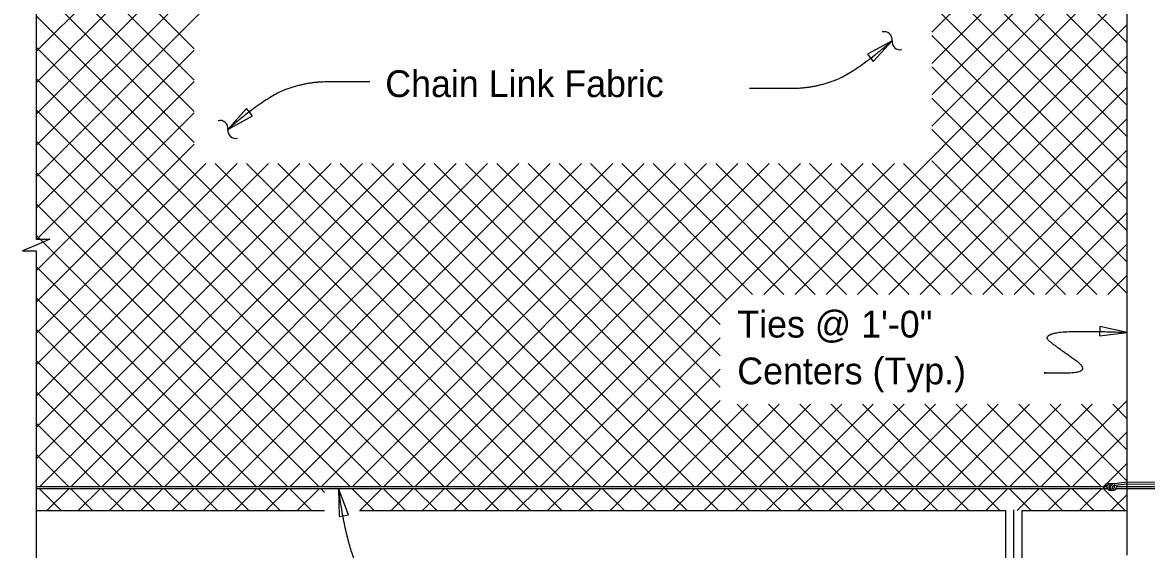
# Model space of a CAD drawing. Extents: x 0 to 41.1, y 0 to 25.9.
# Drawn here: x 16.15 to 24.62, y 16.93 to 20.9 of the extents above; entities that cross this region are included whole.
import ezdxf

# ---------------------------------------------------------------- set-up
doc = ezdxf.new("R2010")
doc.units = 0
for name, color, linetype in [('CL_Major', 7, 'Continuous'), ('Dimension', 7, 'Continuous'), ('Miscellaneous', 7, 'Continuous'), ('SteelMisc', 7, 'Continuous'), ('SteelMisc_h', 7, 'Continuous'), ('SupstrConc', 7, 'Continuous'), ('TextStructures', 7, 'Continuous')]:
    doc.layers.add(name, color=color, linetype=linetype)

msp = doc.modelspace()

# ---------------------------------------------------------------- linework, layer by layer
at = {"layer": 'CL_Major'}
msp.add_line((23.6151, 11.6734), (23.6151, 17.2313), dxfattribs=at)
at = {"layer": 'Dimension'}
for points in [[(16.252, 23.2265), (16.252, 21.2702), (16.3553, 21.2702), (16.252, 21.2252), (16.1487, 21.1802), (16.252, 21.1802), (16.252, 20.2867)], [(16.252, 20.2867), (16.252, 19.2689), (16.3553, 19.2689), (16.252, 19.2239), (16.1487, 19.1789), (16.252, 19.1789), (16.252, 16.9746)], [(16.252, 17.2246), (16.252, 15.3737), (16.3553, 15.3737), (16.252, 15.3287), (16.1487, 15.2837), (16.252, 15.2837), (16.252, 13.2829)]]:
    msp.add_lwpolyline(points, dxfattribs=at)
for points in [[(22.699, 20.7612), (22.5135, 20.6603), (22.5571, 20.6048)], [(17.695, 20.0946), (17.8805, 20.1956), (17.8369, 20.251)], [(24.4692, 18.5661), (24.2626, 18.6099), (24.2597, 18.5394)], [(18.5297, 17.3912), (18.5346, 17.18), (18.6039, 17.1934)]]:
    msp.add_lwpolyline(points, close=True, dxfattribs=at)
for centre, start, end in [((22.6394, 20.7697), 352.34263, 104.06985), ((22.7576, 20.7538), 172.34263, 284.06985), ((17.6364, 20.102), 352.34263, 104.06985), ((17.7546, 20.0861), 172.34263, 284.06985)]:
    msp.add_arc(centre, 0.0596, start, end, dxfattribs=at)
for points in [[(21.6258, 20.4048), (21.8279, 20.4048), (22.1015, 20.4048), (22.4083, 20.5127), (22.6984, 20.7617)], [(18.7638, 20.451), (18.5661, 20.451), (18.2925, 20.451), (17.9858, 20.3431), (17.6956, 20.0941)], [(23.8587, 18.2615), (23.7933, 18.2615), (24.2134, 18.2615), (23.9631, 18.4386), (23.826, 18.5413), (24.0365, 18.5838), (24.4692, 18.5661)], [(19.1927, 16.5972), (18.7949, 16.5972), (18.5909, 16.9342), (18.5297, 17.3911)]]:
    msp.add_open_spline(points, degree=2, dxfattribs=at)
at = {"layer": 'Miscellaneous'}
for p, q in [((16.252, 19.7364), (19.5586, 23.0431)), ((16.252, 20.2078), (19.0872, 23.0431)), ((16.252, 20.6792), (18.6158, 23.0431)), ((16.252, 19.9721), (19.3229, 23.0431)), ((16.252, 20.4435), (18.8515, 23.0431)), ((20.9925, 23.0431), (24.4692, 19.5664)), ((21.2282, 23.0431), (24.4692, 19.8021)), ((21.4639, 23.0431), (24.4692, 20.0378)), ((21.6996, 23.0431), (24.4692, 20.2735)), ((21.9353, 23.0431), (24.4692, 20.5092)), ((22.1711, 23.0431), (24.4692, 20.7449)), ((22.9985, 20.8261), (24.4692, 22.2968)), ((22.9985, 20.5904), (24.4692, 22.0611)), ((16.252, 21.8911), (17.4417, 20.7014)), ((22.9985, 20.3547), (24.4692, 21.8254)), ((16.252, 21.6554), (17.4417, 20.4657)), ((22.9985, 20.119), (24.4692, 21.5897)), ((16.252, 21.4197), (17.4417, 20.23)), ((21.9677, 18.8525), (24.4692, 21.354)), ((16.2232, 21.2127), (17.4417, 19.9943)), ((22.2034, 18.8525), (24.4692, 21.1183)), ((16.252, 20.9483), (19.7943, 17.4059)), ((22.4391, 18.8525), (24.4692, 20.8826)), ((22.9985, 20.8014), (24.4692, 19.3307)), ((16.252, 20.7126), (19.5586, 17.4059)), ((16.252, 19.5007), (17.4417, 20.6904)), ((22.6748, 18.8525), (24.4692, 20.6469)), ((22.9985, 20.5657), (24.4692, 19.095)), ((16.252, 20.4769), (19.3229, 17.4059)), ((16.2558, 19.2689), (17.4417, 20.4547)), ((22.9105, 18.8525), (24.4692, 20.4112)), ((22.9985, 20.33), (24.4692, 18.8593)), ((16.252, 20.2412), (19.0872, 17.4059)), ((16.252, 19.0293), (17.4417, 20.219)), ((23.1462, 18.8525), (24.4692, 20.1755)), ((22.9985, 20.0943), (24.2403, 18.8525)), ((16.252, 20.0055), (18.8515, 17.4059)), ((16.252, 18.7936), (17.4417, 19.9833)), ((23.3819, 18.8525), (24.4692, 19.9398)), ((16.252, 17.8508), (18.2378, 19.8366)), ((16.252, 18.3222), (17.7664, 19.8366)), ((16.252, 18.5579), (17.5307, 19.8366)), ((16.252, 18.0865), (18.0021, 19.8366)), ((16.252, 17.6151), (18.4735, 19.8366)), ((16.2785, 17.4059), (18.7092, 19.8366)), ((16.5142, 17.4059), (18.9449, 19.8366)), ((16.7499, 17.4059), (19.1806, 19.8366)), ((16.9856, 17.4059), (19.4163, 19.8366)), ((17.2213, 17.4059), (19.652, 19.8366)), ((17.457, 17.4059), (19.8877, 19.8366)), ((17.5994, 19.8366), (20.03, 17.4059)), ((17.6927, 17.4059), (20.1234, 19.8366)), ((17.8351, 19.8366), (20.2657, 17.4059)), ((17.9284, 17.4059), (20.3591, 19.8366)), ((18.0708, 19.8366), (20.5014, 17.4059)), ((18.1641, 17.4059), (20.5948, 19.8366)), ((18.3065, 19.8366), (20.7372, 17.4059)), ((18.3998, 17.4059), (20.8305, 19.8366)), ((18.5422, 19.8366), (21.0907, 17.2881)), ((18.6355, 17.4059), (21.0662, 19.8366)), ((18.7779, 19.8366), (21.2086, 17.4059)), ((18.8712, 17.4059), (21.3019, 19.8366)), ((19.0136, 19.8366), (21.4443, 17.4059)), ((19.1069, 17.4059), (21.5376, 19.8366)), ((19.2493, 19.8366), (21.68, 17.4059)), ((19.3426, 17.4059), (21.7733, 19.8366)), ((19.485, 19.8366), (21.9157, 17.4059)), ((19.5783, 17.4059), (22.009, 19.8366)), ((19.6962, 17.2881), (22.2447, 19.8366)), ((19.7207, 19.8366), (21.4039, 18.1533)), ((19.9564, 19.8366), (21.4039, 18.389)), ((20.0497, 17.4059), (22.4804, 19.8366)), ((20.1921, 19.8366), (21.4039, 18.6247)), ((20.4278, 19.8366), (21.4541, 18.8103)), ((20.6635, 19.8366), (21.6476, 18.8525)), ((20.8992, 19.8366), (21.8833, 18.8525)), ((21.1349, 19.8366), (22.119, 18.8525)), ((21.3706, 19.8366), (22.3547, 18.8525)), ((21.6063, 19.8366), (22.5904, 18.8525)), ((21.732, 18.8525), (22.7161, 19.8366)), ((21.842, 19.8366), (22.8261, 18.8525)), ((22.0777, 19.8366), (23.0618, 18.8525)), ((22.3134, 19.8366), (23.2975, 18.8525)), ((22.5491, 19.8366), (23.5332, 18.8525)), ((22.7848, 19.8366), (23.7689, 18.8525)), ((22.9985, 19.8586), (24.0046, 18.8525)), ((16.252, 19.7698), (18.6158, 17.4059)), ((23.6176, 18.8525), (24.4692, 19.7041)), ((16.252, 19.5341), (18.3801, 17.4059)), ((23.8533, 18.8525), (24.4692, 19.4684)), ((16.252, 19.2984), (18.1444, 17.4059)), ((24.089, 18.8525), (24.4692, 19.2327)), ((16.252, 19.0627), (17.9087, 17.4059)), ((24.3247, 18.8525), (24.4692, 18.997)), ((16.252, 18.827), (17.673, 17.4059)), ((16.252, 18.5913), (17.4373, 17.4059)), ((20.2854, 17.4059), (21.4039, 18.5244)), ((16.252, 18.3556), (17.2016, 17.4059)), ((20.5211, 17.4059), (21.4039, 18.2887)), ((16.252, 18.1198), (16.9659, 17.4059)), ((20.7568, 17.4059), (21.4039, 18.053)), ((23.821, 17.4059), (24.4692, 18.0542)), ((20.9925, 17.4059), (21.6122, 18.0255)), ((21.2282, 17.4059), (21.8479, 18.0255)), ((21.4639, 17.4059), (22.0836, 18.0255)), ((21.5318, 18.0255), (22.1514, 17.4059)), ((21.6996, 17.4059), (22.3193, 18.0255)), ((21.7675, 18.0255), (22.3871, 17.4059)), ((21.9353, 17.4059), (22.555, 18.0255)), ((22.0032, 18.0255), (22.6228, 17.4059)), ((22.1711, 17.4059), (22.7907, 18.0255)), ((22.2389, 18.0255), (22.8585, 17.4059)), ((22.4068, 17.4059), (23.0264, 18.0255)), ((22.4746, 18.0255), (23.0942, 17.4059)), ((22.6425, 17.4059), (23.2621, 18.0255)), ((22.7103, 18.0255), (23.3299, 17.4059)), ((22.8782, 17.4059), (23.4978, 18.0255)), ((22.946, 18.0255), (23.5656, 17.4059)), ((23.1139, 17.4059), (23.7335, 18.0255)), ((23.1817, 18.0255), (23.8013, 17.4059)), ((23.3496, 17.4059), (23.9692, 18.0255)), ((23.4174, 18.0255), (24.037, 17.4059)), ((23.5853, 17.4059), (24.2049, 18.0255)), ((23.6531, 18.0255), (24.2727, 17.4059)), ((23.8888, 18.0255), (24.4692, 17.4451)), ((24.1245, 18.0255), (24.4692, 17.6808)), ((24.3602, 18.0255), (24.4692, 17.9165)), ((16.252, 17.8841), (16.7302, 17.4059)), ((24.0567, 17.4059), (24.4692, 17.8185)), ((16.252, 17.6484), (16.4945, 17.4059)), ((24.3083, 17.4218), (24.4692, 17.5828)), ((16.2736, 17.3912), (16.4402, 17.2245)), ((16.3328, 17.2245), (16.4994, 17.3912)), ((16.5093, 17.3912), (16.6759, 17.2245)), ((16.5685, 17.2245), (16.7352, 17.3912)), ((16.745, 17.3912), (16.9116, 17.2245)), ((16.8042, 17.2245), (16.9709, 17.3912)), ((16.9807, 17.3912), (17.1473, 17.2245)), ((17.0399, 17.2245), (17.2066, 17.3912)), ((17.2164, 17.3912), (17.383, 17.2245)), ((17.2756, 17.2245), (17.4423, 17.3912)), ((17.4521, 17.3912), (17.6187, 17.2245)), ((17.5113, 17.2245), (17.678, 17.3912)), ((17.6878, 17.3912), (17.8544, 17.2245)), ((17.747, 17.2245), (17.9137, 17.3912)), ((17.9235, 17.3912), (18.0901, 17.2245)), ((17.9827, 17.2245), (18.1494, 17.3912)), ((18.1592, 17.3912), (18.3258, 17.2245)), ((18.2184, 17.2245), (18.3851, 17.3912)), ((18.3949, 17.3912), (18.424, 17.3621)), ((18.6306, 17.3912), (18.7972, 17.2245)), ((18.6898, 17.2245), (18.8565, 17.3912)), ((18.8663, 17.3912), (19.0329, 17.2245)), ((18.9255, 17.2245), (19.0922, 17.3912)), ((19.102, 17.3912), (19.2687, 17.2245)), ((19.1612, 17.2245), (19.3279, 17.3912)), ((19.3377, 17.3912), (19.5044, 17.2245)), ((19.3969, 17.2245), (19.5636, 17.3912)), ((19.5734, 17.3912), (19.7401, 17.2245)), ((19.6326, 17.2245), (19.7993, 17.3912)), ((19.8091, 17.3912), (19.9758, 17.2245)), ((19.8683, 17.2245), (20.035, 17.3912)), ((20.0448, 17.3912), (20.2115, 17.2245)), ((20.104, 17.2245), (20.2707, 17.3912)), ((20.2805, 17.3912), (20.4472, 17.2245)), ((20.3397, 17.2245), (20.5064, 17.3912)), ((20.5162, 17.3912), (20.6829, 17.2245)), ((20.5754, 17.2245), (20.7421, 17.3912)), ((20.7519, 17.3912), (20.9186, 17.2245)), ((20.8111, 17.2245), (20.9778, 17.3912)), ((20.9876, 17.3912), (21.1543, 17.2245)), ((21.0468, 17.2245), (21.2135, 17.3912)), ((21.2233, 17.3912), (21.39, 17.2245)), ((21.2825, 17.2245), (21.4492, 17.3912)), ((21.459, 17.3912), (21.6257, 17.2245)), ((21.5182, 17.2245), (21.6849, 17.3912)), ((21.6947, 17.3912), (21.8614, 17.2245)), ((21.7539, 17.2245), (21.9206, 17.3912)), ((21.9304, 17.3912), (22.0971, 17.2245)), ((21.9896, 17.2245), (22.1563, 17.3912)), ((22.1661, 17.3912), (22.3328, 17.2245)), ((22.2253, 17.2245), (22.392, 17.3912)), ((22.4018, 17.3912), (22.5685, 17.2245)), ((22.461, 17.2245), (22.6277, 17.3912)), ((22.6375, 17.3912), (22.8042, 17.2245)), ((22.6967, 17.2245), (22.8634, 17.3912)), ((22.8732, 17.3912), (23.0399, 17.2245)), ((22.9324, 17.2245), (23.0991, 17.3912)), ((23.1089, 17.3912), (23.2756, 17.2245)), ((23.1681, 17.2245), (23.3348, 17.3912)), ((23.3446, 17.3912), (23.5113, 17.2245)), ((23.4038, 17.2245), (23.5705, 17.3912)), ((23.5803, 17.3912), (23.747, 17.2245)), ((23.6396, 17.2245), (23.8062, 17.3912)), ((23.816, 17.3912), (23.9827, 17.2245)), ((23.8753, 17.2245), (24.0419, 17.3912)), ((24.0517, 17.3912), (24.2184, 17.2245)), ((24.111, 17.2245), (24.2776, 17.3912)), ((24.2874, 17.3912), (24.4541, 17.2245)), ((24.2924, 17.4059), (24.296, 17.4095)), ((24.3467, 17.2245), (24.4692, 17.3471))]:
    msp.add_line(p, q, dxfattribs=at)
at = {"layer": 'SteelMisc'}
for p, q in [((24.4692, 16.8894), (24.4692, 23.2644)), ((16.252, 17.4059), (24.2941, 17.4059)), ((16.252, 17.3912), (24.3207, 17.3912)), ((24.304, 17.4059), (24.3172, 17.4059)), ((24.4692, 17.4385), (24.3743, 17.4274)), ((24.4692, 17.424), (24.3766, 17.4145)), ((24.3856, 17.3912), (24.4692, 17.3912)), ((24.387, 17.4059), (24.4692, 17.4059)), ((24.4692, 17.4385), (24.7604, 17.4402)), ((24.4692, 17.424), (24.7604, 17.4257))]:
    msp.add_line(p, q, dxfattribs=at)
for centre, major_axis, ratio, start_param, end_param in [((24.3283, 17.3916), (0.0373, 0), 0.957868, 1.486836, 3.108042), ((24.3494, 17.3519), (-0.0724, 0), 0.957868, 5.162149, 5.652106), ((24.3419, 17.4036), (-0.0249, 0), 0.957868, 6.009018, 7.089857), ((24.3408, 17.4061), (0.023, 0), 0.957868, 1.29026, 2.970541), ((24.3433, 17.3996), (0.0231, 0), 0.957868, 3.779554, 4.879821), ((24.3595, 17.4007), (0.0295, 0), 0.957868, 1.220941, 4.039556), ((24.373, 17.4025), (-0.0303, -0.0108), 0.724765, 4.35367, 6.324556), ((24.3494, 17.3939), (0.0206, -0.0021), 0.798607, 4.32653, 5.220153), ((24.3629, 17.3939), (0.0206, -0.0021), 0.798607, 3.333154, 5.220153), ((24.3697, 17.3985), (-0.0139, 0), 0.957868, 5.22362, 6.905413), ((24.364, 17.3961), (-0.00795, 0), 0.957868, 6.140374, 9.314262), ((24.3781, 17.3896), (-0.0259, 0), 0.957868, 4.777514, 5.62749), ((24.3624, 17.4019), (0.0119, 0), 0.957868, 5.725876, 7.416677), ((24.3555, 17.4127), (0.0391, 0), 0.957868, 5.082588, 5.41974), ((24.3624, 17.4019), (0.0119, 0), 0.957868, 5.639684, 5.723117), ((24.3626, 17.4006), (0.0251, 0), 0.957868, 5.531357, 6.227833), ((24.3626, 17.4006), (0.0251, 0), 0.957868, 0.407687, 0.609214)]:
    msp.add_ellipse(centre, major_axis=major_axis, ratio=ratio, start_param=start_param, end_param=end_param, dxfattribs=at)
at = {"layer": 'SteelMisc_h'}
for p, q in [((24.4692, 17.4059), (24.7609, 17.4059)), ((24.4692, 17.3912), (24.7609, 17.3912))]:
    msp.add_line(p, q, dxfattribs=at)
at = {"layer": 'SupstrConc'}
for p, q in [((16.252, 17.2245), (18.424, 17.2245)), ((18.6879, 17.2245), (23.5538, 17.2245)), ((23.5538, 17.2245), (23.5538, 12.7032)), ((23.6763, 17.2245), (23.6763, 13.8912)), ((23.6763, 17.2245), (24.4692, 17.2245))]:
    msp.add_line(p, q, dxfattribs=at)

# ---------------------------------------------------------------- texts
at = {"layer": 'Dimension'}
for s, p in [('Ties @ 1\'-0" ', (21.5326, 18.5274)), ('Centers (Typ.)', (21.5326, 18.1754))]:
    msp.add_text(s, height=0.2016, dxfattribs=at).set_placement(p)
at = {"layer": 'TextStructures'}
msp.add_text('Chain Link Fabric', height=0.2016, dxfattribs=at).set_placement((18.8811, 20.3373))

doc.saveas('drawing.dxf')
